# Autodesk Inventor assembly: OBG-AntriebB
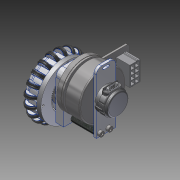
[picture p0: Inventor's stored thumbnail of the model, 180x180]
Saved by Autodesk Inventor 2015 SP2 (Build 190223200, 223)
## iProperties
Created: 2012-07
Part Number: OBG-AntriebB
Document SubType Name: Assembly
Designer: rYan
Mass: 389.044 g
Surface Area: 554.19 cm^2
Volume: 67.7043 cm^3
Density: 5.74622 g/cm^3
Author: rYan
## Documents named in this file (12)
- D:\TIGERs GIT\Hardware\mechanik\2016\Inventor\Antrieb\OBG-AntriebB.iam
- D:\TIGERs GIT\Hardware\mechanik\2016\Inventor\Antrieb\UBG-Rad.iam
- D:\TIGERs GIT\Hardware\mechanik\2016\Inventor\Inhaltscenter\de-DE\DIN 7984\DIN 7984 - M3 x 8.ipt
- D:\TIGERs GIT\Hardware\mechanik\2016\Inventor\Antrieb\Lagerbock.ipt
- D:\TIGERs GIT\Hardware\mechanik\2016\Inventor\Kaufteile\Abstandsbolzen Typ B M2.5-22mm.ipt
- D:\Tigers SVN\mechanik\2016\Inventor\Kaufteile\Abstandsbolzen Typ B.ipt
- D:\TIGERs GIT\Hardware\mechanik\2016\Inventor\Antrieb\Encoderhalter.ipt
- D:\TIGERs GIT\Hardware\mechanik\2016\Inventor\Kaufteile\MG-MaxonEC45-50W.iam
- D:\TIGERs GIT\Hardware\mechanik\2016\Inventor\Kaufteile\E8P-X-157-S-D-M-X\E8P-X-157-S-D-M-X.iam
- D:\TIGERs GIT\Hardware\mechanik\2016\Inventor\Inhaltscenter\de-DE\ISO 4762(1)\ISO 4762 - M2,5 x 6DIN EN ISO.ipt
- D:\TIGERs GIT\Hardware\mechanik\2016\Inventor\Kaufteile\Ritzel z18.ipt
- D:\TIGERs GIT\Hardware\mechanik\2016\Inventor\Kaufteile\E4T-X-157-S-D-M-X\E4T-X-157-S-D-M-X.iam
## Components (16 placed, 10 different names)
1. Lagerbock:1 — Passend:17, Passend:21, Passend:22, Passend:23, Passend:24, Passend:25, Passend:26
2. MG-MaxonEC45-50W:1 [sub-assembly] — Einfügen:1
3. Ritzel z=18:1 — Einfügen:1
4. UBG-Rad:1 [sub-assembly] — Passend:21, Passend:22, Winkel:1
5. Abstandsbolzen Typ B M2.5-22mm:1 — Passend:23, Passend:25, Passend:42
6. Abstandsbolzen Typ B M2.5-22mm:2 — Passend:24, Passend:26, Passend:41, Passend:43
7. Encoderhalter:1 — Passend:41, Passend:42, Passend:43, Passend:44, Passend:45, Passend:46, Passend:47, Passend:48, Passend:49, Passend:50, Einfügen:2, Winkel:2
8. E8P-X-157-S-D-M-X:1 [sub-assembly] — Passend:39, Passend:40, Passend:48, Passend:49, Passend:50, Passend:51, Passend:52
9. DIN EN ISO 4762 M2,5 x 6:1 — Passend:44, Passend:46
10. DIN EN ISO 4762 M2,5 x 6:2 — Passend:45, Passend:47
11. DIN EN ISO 4762 M2,5 x 6:3 — Passend:39, Passend:52
12. DIN EN ISO 4762 M2,5 x 6:4 — Passend:40, Passend:51
13. E4T-X-157-S-D-M-X:1 [sub-assembly] — Einfügen:2, Winkel:2
14. DIN 7984 M3 x 8:1 — Passend:17
15. DIN 7984 M3 x 8:2
16. DIN 7984 M3 x 8:3
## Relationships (25: Mate 21, Angle 2, Insert 2)
- Passend:17 [Mate]: Lagerbock:1 ↔ DIN 7984 M3 x 8:1
- Passend:21 [Mate]: Lagerbock:1 ↔ UBG-Rad:1
- Passend:22 [Mate]: Lagerbock:1 ↔ UBG-Rad:1
- Winkel:1 [Angle]: UBG-Rad:1
- Passend:23 [Mate]: Lagerbock:1 ↔ Abstandsbolzen Typ B M2.5-22mm:1
- Passend:24 [Mate]: Lagerbock:1 ↔ Abstandsbolzen Typ B M2.5-22mm:2
- Passend:25 [Mate]: Lagerbock:1 ↔ Abstandsbolzen Typ B M2.5-22mm:1
- Passend:26 [Mate]: Lagerbock:1 ↔ Abstandsbolzen Typ B M2.5-22mm:2
- Passend:39 [Mate]: E8P-X-157-S-D-M-X:1 ↔ DIN EN ISO 4762 M2,5 x 6:3
- Passend:40 [Mate]: E8P-X-157-S-D-M-X:1 ↔ DIN EN ISO 4762 M2,5 x 6:4
- Passend:41 [Mate]: Abstandsbolzen Typ B M2.5-22mm:2 ↔ Encoderhalter:1
- Passend:42 [Mate]: Abstandsbolzen Typ B M2.5-22mm:1 ↔ Encoderhalter:1
- Passend:43 [Mate]: Abstandsbolzen Typ B M2.5-22mm:2 ↔ Encoderhalter:1
- Passend:44 [Mate]: Encoderhalter:1 ↔ DIN EN ISO 4762 M2,5 x 6:1
- Passend:45 [Mate]: Encoderhalter:1 ↔ DIN EN ISO 4762 M2,5 x 6:2
- Passend:46 [Mate]: Encoderhalter:1 ↔ DIN EN ISO 4762 M2,5 x 6:1
- Passend:47 [Mate]: Encoderhalter:1 ↔ DIN EN ISO 4762 M2,5 x 6:2
- Passend:48 [Mate]: Encoderhalter:1 ↔ E8P-X-157-S-D-M-X:1
- Passend:49 [Mate]: Encoderhalter:1 ↔ E8P-X-157-S-D-M-X:1
- Passend:50 [Mate]: Encoderhalter:1 ↔ E8P-X-157-S-D-M-X:1
- Einfügen:1 [Insert]: MG-MaxonEC45-50W:1 ↔ Ritzel z=18:1
- Passend:51 [Mate]: E8P-X-157-S-D-M-X:1 ↔ DIN EN ISO 4762 M2,5 x 6:4
- Passend:52 [Mate]: E8P-X-157-S-D-M-X:1 ↔ DIN EN ISO 4762 M2,5 x 6:3
- Einfügen:2 [Insert]: Encoderhalter:1 ↔ E4T-X-157-S-D-M-X:1
- Winkel:2 [Angle]: Encoderhalter:1 ↔ E4T-X-157-S-D-M-X:1
